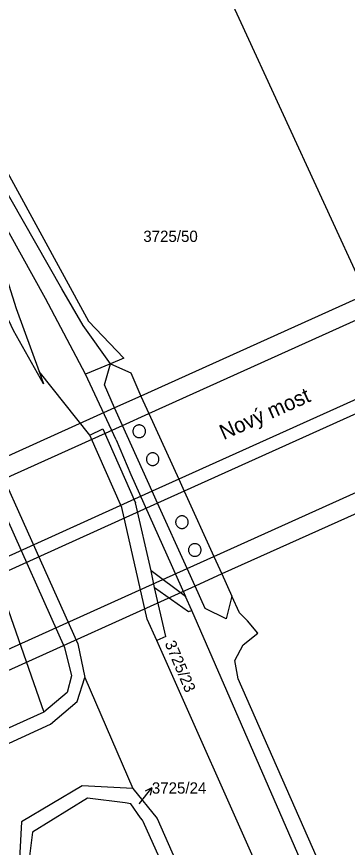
# Model space of a CAD drawing. Extents: x -747779 to -747197, y -965543 to -964919.
# Drawn here: x -747440.7 to -747390.8, y -965475 to -965349.9 of the extents above; entities that cross this region are included whole.
import ezdxf

# ---------------------------------------------------------------- set-up
doc = ezdxf.new("R2010")
doc.units = 0
for name, color, linetype in [('Hranice parcel', 7, 'Continuous'), ('Parcelní čísla', 7, 'Continuous'), ('Pop  PČ popisy', 7, 'Continuous'), ('Vnitřní kresba', 7, 'Continuous')]:
    doc.layers.add(name, color=color, linetype=linetype)

msp = doc.modelspace()

# ---------------------------------------------------------------- linework, layer by layer
at = {"layer": 'Hranice parcel'}
for p, q in [((-747442.75, -965437.1), (-747436.62, -965454.67)), ((-747430.45, -965449.46), (-747423.22, -965466.19))]:
    msp.add_line(p, q, dxfattribs=at)
for points in [[(-747298.39, -965537.69), (-747318.1, -965501.72), (-747320.58, -965502.66), (-747342.67, -965465.16), (-747352.78, -965470.55), (-747357.13, -965461.03), (-747376, -965418.63), (-747377.18, -965415.98), (-747381.59, -965406.09), (-747382.39, -965404.29), (-747386.82, -965394.33), (-747387.63, -965392.51), (-747387.99, -965391.72), (-747426.3, -965308.51), (-747438.98, -965282.25)], [(-747481.32, -965290.75), (-747467.96, -965317.93), (-747448.87, -965361), (-747429.89, -965395.74), (-747424.56, -965401.33), (-747426.57, -965402.17)], [(-747437.34, -965403.35), (-747436.67, -965405.18), (-747441.17, -965397.15), (-747449.31, -965379.9), (-747457.39, -965360.59), (-747463.67, -965351.63), (-747474.03, -965344.07), (-747481.12, -965327.83), (-747494.62, -965293.42)], [(-747580, -965419.59), (-747576.93, -965416.19), (-747570.41, -965408.98), (-747568.93, -965407.34), (-747555.66, -965395.12), (-747533.62, -965375.09), (-747516.44, -965363.14), (-747498.44, -965358.86), (-747484.39, -965361.2), (-747471.99, -965367.52), (-747464.29, -965374.98), (-747459.13, -965383.85), (-747452.93, -965401.54), (-747433.5, -965444.94), (-747432.43, -965449.21), (-747433.12, -965451.71), (-747436.62, -965454.67)], [(-747426.57, -965402.17), (-747430.32, -965403.74), (-747436.36, -965392.33), (-747443.64, -965379.27), (-747445.23, -965379.92)], [(-747445.23, -965379.92), (-747440.81, -965393.86), (-747437.34, -965403.35)], [(-747457, -965384.11), (-747451.17, -965400.56), (-747431.47, -965444.37), (-747430.45, -965449.46)], [(-747425.95, -965408.84), (-747427.45, -965405.35), (-747426.57, -965402.17)], [(-747421.02, -965440.66), (-747424.84, -965423.83), (-747429.68, -965412.94), (-747437.34, -965403.35)], [(-747413.8, -965435.67), (-747414.99, -965433.04), (-747419.46, -965423.17), (-747420.28, -965421.37), (-747424.76, -965411.47), (-747425.95, -965408.84)], [(-747370.93, -965537.69), (-747371.14, -965534.42), (-747371.37, -965533), (-747372.01, -965529.87), (-747376.13, -965520.36), (-747382.27, -965506.43), (-747407.33, -965449.67), (-747407.84, -965446.87), (-747406.56, -965444.53), (-747404.36, -965442.75), (-747405.91, -965440.89), (-747407.09, -965439.7), (-747408.25, -965437.2), (-747409.14, -965440.59), (-747412.27, -965439.07), (-747413.8, -965435.67)], [(-747377.11, -965537.69), (-747403.05, -965481.03), (-747419.59, -965443.86), (-747421.02, -965440.66)], [(-747447.33, -965460.58), (-747441.86, -965459.33), (-747435.59, -965456.49), (-747431.61, -965453.05), (-747430.45, -965449.46)], [(-747436.62, -965454.67), (-747442.27, -965457.24), (-747448.67, -965457.93), (-747450.38, -965456.32)], [(-747423.22, -965466.19), (-747430.85, -965465.78), (-747440, -965471.21), (-747440.51, -965480.52)], [(-747423.22, -965466.19), (-747419.51, -965470.69), (-747413.64, -965484.08), (-747404.72, -965503.92), (-747389.51, -965537.69)], [(-747391.7, -965537.69), (-747398.54, -965522.5), (-747406.47, -965504.9), (-747415.34, -965485.13), (-747421.64, -965471.15), (-747421.73, -965470.95), (-747422.02, -965470.6), (-747423.51, -965468.47), (-747424.37, -965468.36), (-747430.04, -965467.62), (-747438.32, -965472.78), (-747439.08, -965478.79), (-747440.51, -965480.52)]]:
    msp.add_lwpolyline(points, dxfattribs=at)
at = {"layer": 'Pop  PČ popisy'}
for p, q in [((-747422.19, -965468.46), (-747420.34, -965466.09)), ((-747420.34, -965466.09), (-747421.35, -965466.58)), ((-747420.34, -965466.09), (-747420.56, -965467.19)), ((-747422.23, -965468.51), (-747422.19, -965468.46))]:
    msp.add_line(p, q, dxfattribs=at)
at = {"layer": 'Vnitřní kresba'}
for p, q in [((-747433.91, -965390.91), (-747444.82, -965371.76)), ((-747430.68, -965396.39), (-747433.91, -965390.91)), ((-747387.99, -965391.72), (-747421.99, -965407.05)), ((-747420.79, -965409.68), (-747386.82, -965394.33)), ((-747426.57, -965402.17), (-747430.68, -965396.39)), ((-747426.57, -965402.17), (-747423.49, -965403.54)), ((-747425.73, -965413.62), (-747430.32, -965403.74)), ((-747423.49, -965403.54), (-747421.99, -965407.05)), ((-747382.39, -965404.29), (-747416.28, -965419.57)), ((-747381.59, -965406.09), (-747415.46, -965421.36)), ((-747421.99, -965407.05), (-747425.95, -965408.84)), ((-747421.99, -965407.05), (-747420.79, -965409.68)), ((-747425.95, -965408.84), (-747511.58, -965447.46)), ((-747424.76, -965411.47), (-747420.79, -965409.68)), ((-747420.79, -965409.68), (-747416.28, -965419.57)), ((-747510.38, -965450.13), (-747424.76, -965411.47)), ((-747429.68, -965412.94), (-747427.74, -965412)), ((-747427.74, -965412), (-747422.79, -965423.13)), ((-747425.73, -965413.62), (-747423.52, -965418.88)), ((-747410.96, -965431.22), (-747377.18, -965415.98)), ((-747423.52, -965418.88), (-747415.25, -965437.24)), ((-747376, -965418.63), (-747409.76, -965433.85)), ((-747416.28, -965419.57), (-747420.28, -965421.37)), ((-747416.28, -965419.57), (-747415.46, -965421.36)), ((-747420.28, -965421.37), (-747505.95, -965460)), ((-747415.46, -965421.36), (-747419.46, -965423.17)), ((-747415.46, -965421.36), (-747410.96, -965431.22)), ((-747419.46, -965423.17), (-747505.13, -965461.82)), ((-747420.45, -965433.4), (-747422.79, -965423.13)), ((-747414.99, -965433.04), (-747410.96, -965431.22)), ((-747410.96, -965431.22), (-747409.76, -965433.85)), ((-747500.73, -965471.63), (-747414.99, -965433.04)), ((-747419.91, -965435.87), (-747420.45, -965433.4)), ((-747415.25, -965437.24), (-747420.45, -965433.4)), ((-747409.76, -965433.85), (-747413.8, -965435.67)), ((-747409.76, -965433.85), (-747408.25, -965437.2)), ((-747413.8, -965435.67), (-747499.51, -965474.39)), ((-747418.24, -965443.28), (-747419.91, -965435.87)), ((-747419.91, -965435.87), (-747414.81, -965439.52)), ((-747414.31, -965439.35), (-747415.25, -965437.24)), ((-747414.81, -965439.52), (-747414.31, -965439.35)), ((-747373.33, -965533.21), (-747414.31, -965439.35)), ((-747418.24, -965443.28), (-747419.59, -965443.86))]:
    msp.add_line(p, q, dxfattribs=at)
for points in [[(-747422.24, -965411.4), (-747422.33, -965411.4), (-747422.41, -965411.42), (-747422.49, -965411.43), (-747422.57, -965411.46), (-747422.65, -965411.49), (-747422.73, -965411.53), (-747422.8, -965411.58), (-747422.86, -965411.64), (-747422.93, -965411.69), (-747422.98, -965411.76), (-747423.03, -965411.83), (-747423.08, -965411.9), (-747423.11, -965411.98), (-747423.14, -965412.06), (-747423.17, -965412.14), (-747423.18, -965412.22), (-747423.19, -965412.31), (-747423.19, -965412.39), (-747423.18, -965412.48), (-747423.17, -965412.56), (-747423.14, -965412.64), (-747423.11, -965412.72), (-747423.08, -965412.8), (-747423.03, -965412.87), (-747422.98, -965412.94), (-747422.93, -965413.01), (-747422.86, -965413.07), (-747422.8, -965413.12), (-747422.73, -965413.17), (-747422.65, -965413.21), (-747422.57, -965413.24), (-747422.49, -965413.27), (-747422.41, -965413.29), (-747422.33, -965413.3), (-747422.24, -965413.3), (-747422.16, -965413.3), (-747422.07, -965413.29), (-747421.99, -965413.27), (-747421.91, -965413.24), (-747421.83, -965413.21), (-747421.75, -965413.17), (-747421.68, -965413.12), (-747421.61, -965413.07), (-747421.55, -965413.01), (-747421.5, -965412.94), (-747421.45, -965412.87), (-747421.4, -965412.8), (-747421.37, -965412.72), (-747421.34, -965412.64), (-747421.31, -965412.56), (-747421.3, -965412.48), (-747421.29, -965412.39), (-747421.29, -965412.31), (-747421.3, -965412.22), (-747421.31, -965412.14), (-747421.34, -965412.06), (-747421.37, -965411.98), (-747421.4, -965411.9), (-747421.45, -965411.83), (-747421.5, -965411.76), (-747421.55, -965411.69), (-747421.61, -965411.64), (-747421.68, -965411.58), (-747421.75, -965411.53), (-747421.83, -965411.49), (-747421.91, -965411.46), (-747421.99, -965411.43), (-747422.07, -965411.42), (-747422.16, -965411.4)], [(-747420.21, -965415.61), (-747420.3, -965415.61), (-747420.38, -965415.62), (-747420.46, -965415.64), (-747420.54, -965415.67), (-747420.62, -965415.7), (-747420.7, -965415.74), (-747420.77, -965415.79), (-747420.83, -965415.84), (-747420.9, -965415.9), (-747420.95, -965415.97), (-747421, -965416.04), (-747421.05, -965416.11), (-747421.08, -965416.19), (-747421.11, -965416.27), (-747421.14, -965416.35), (-747421.15, -965416.43), (-747421.16, -965416.52), (-747421.16, -965416.6), (-747421.15, -965416.69), (-747421.14, -965416.77), (-747421.11, -965416.85), (-747421.08, -965416.93), (-747421.05, -965417.01), (-747421, -965417.08), (-747420.95, -965417.15), (-747420.9, -965417.22), (-747420.83, -965417.28), (-747420.77, -965417.33), (-747420.7, -965417.38), (-747420.62, -965417.42), (-747420.54, -965417.45), (-747420.46, -965417.48), (-747420.38, -965417.49), (-747420.3, -965417.51), (-747420.21, -965417.51), (-747420.12, -965417.51), (-747420.04, -965417.49), (-747419.96, -965417.48), (-747419.88, -965417.45), (-747419.8, -965417.42), (-747419.72, -965417.38), (-747419.65, -965417.33), (-747419.58, -965417.28), (-747419.52, -965417.22), (-747419.47, -965417.15), (-747419.42, -965417.08), (-747419.37, -965417.01), (-747419.34, -965416.93), (-747419.31, -965416.85), (-747419.28, -965416.77), (-747419.27, -965416.69), (-747419.26, -965416.6), (-747419.26, -965416.52), (-747419.27, -965416.43), (-747419.28, -965416.35), (-747419.31, -965416.27), (-747419.34, -965416.19), (-747419.37, -965416.11), (-747419.42, -965416.04), (-747419.47, -965415.97), (-747419.52, -965415.9), (-747419.58, -965415.84), (-747419.65, -965415.79), (-747419.72, -965415.74), (-747419.8, -965415.7), (-747419.88, -965415.67), (-747419.96, -965415.64), (-747420.04, -965415.62), (-747420.12, -965415.61)], [(-747415.79, -965425.1), (-747415.88, -965425.1), (-747415.96, -965425.11), (-747416.04, -965425.13), (-747416.12, -965425.16), (-747416.2, -965425.19), (-747416.28, -965425.23), (-747416.35, -965425.28), (-747416.42, -965425.33), (-747416.48, -965425.39), (-747416.53, -965425.46), (-747416.58, -965425.53), (-747416.63, -965425.6), (-747416.66, -965425.68), (-747416.69, -965425.76), (-747416.72, -965425.84), (-747416.73, -965425.92), (-747416.74, -965426.01), (-747416.74, -965426.09), (-747416.73, -965426.18), (-747416.72, -965426.26), (-747416.69, -965426.34), (-747416.66, -965426.42), (-747416.63, -965426.5), (-747416.58, -965426.57), (-747416.53, -965426.64), (-747416.48, -965426.71), (-747416.42, -965426.77), (-747416.35, -965426.82), (-747416.28, -965426.87), (-747416.2, -965426.91), (-747416.12, -965426.94), (-747416.04, -965426.97), (-747415.96, -965426.98), (-747415.88, -965427), (-747415.79, -965427), (-747415.7, -965427), (-747415.62, -965426.98), (-747415.54, -965426.97), (-747415.46, -965426.94), (-747415.38, -965426.91), (-747415.3, -965426.87), (-747415.23, -965426.82), (-747415.17, -965426.77), (-747415.1, -965426.71), (-747415.05, -965426.64), (-747415, -965426.57), (-747414.95, -965426.5), (-747414.92, -965426.42), (-747414.89, -965426.34), (-747414.86, -965426.26), (-747414.85, -965426.18), (-747414.84, -965426.09), (-747414.84, -965426.01), (-747414.85, -965425.92), (-747414.86, -965425.84), (-747414.89, -965425.76), (-747414.92, -965425.68), (-747414.95, -965425.6), (-747415, -965425.53), (-747415.05, -965425.46), (-747415.1, -965425.39), (-747415.17, -965425.33), (-747415.23, -965425.28), (-747415.3, -965425.23), (-747415.38, -965425.19), (-747415.46, -965425.16), (-747415.54, -965425.13), (-747415.62, -965425.11), (-747415.7, -965425.1)], [(-747413.85, -965429.29), (-747413.94, -965429.29), (-747414.02, -965429.31), (-747414.1, -965429.32), (-747414.18, -965429.35), (-747414.26, -965429.38), (-747414.34, -965429.42), (-747414.41, -965429.47), (-747414.47, -965429.53), (-747414.54, -965429.58), (-747414.59, -965429.65), (-747414.64, -965429.72), (-747414.69, -965429.79), (-747414.72, -965429.87), (-747414.75, -965429.95), (-747414.78, -965430.03), (-747414.79, -965430.11), (-747414.8, -965430.2), (-747414.8, -965430.28), (-747414.79, -965430.37), (-747414.78, -965430.45), (-747414.75, -965430.53), (-747414.72, -965430.61), (-747414.69, -965430.69), (-747414.64, -965430.76), (-747414.59, -965430.83), (-747414.54, -965430.9), (-747414.47, -965430.96), (-747414.41, -965431.01), (-747414.34, -965431.06), (-747414.26, -965431.1), (-747414.18, -965431.13), (-747414.1, -965431.16), (-747414.02, -965431.18), (-747413.94, -965431.19), (-747413.85, -965431.19), (-747413.77, -965431.19), (-747413.68, -965431.18), (-747413.6, -965431.16), (-747413.52, -965431.13), (-747413.44, -965431.1), (-747413.36, -965431.06), (-747413.29, -965431.01), (-747413.22, -965430.96), (-747413.16, -965430.9), (-747413.11, -965430.83), (-747413.06, -965430.76), (-747413.01, -965430.69), (-747412.98, -965430.61), (-747412.95, -965430.53), (-747412.92, -965430.45), (-747412.91, -965430.37), (-747412.9, -965430.28), (-747412.9, -965430.2), (-747412.91, -965430.11), (-747412.92, -965430.03), (-747412.95, -965429.95), (-747412.98, -965429.87), (-747413.01, -965429.79), (-747413.06, -965429.72), (-747413.11, -965429.65), (-747413.16, -965429.58), (-747413.22, -965429.53), (-747413.29, -965429.47), (-747413.36, -965429.42), (-747413.44, -965429.38), (-747413.52, -965429.35), (-747413.6, -965429.32), (-747413.68, -965429.31), (-747413.77, -965429.29)]]:
    msp.add_lwpolyline(points, close=True, dxfattribs=at)

# ---------------------------------------------------------------- texts
at = {"layer": 'Parcelní čísla'}
for s, p in [('3725/50', (-747421.62, -965383.82)), ('3725/24', (-747420.33, -965466.95))]:
    msp.add_text(s, height=1.7, dxfattribs=at).set_placement(p)
msp.add_text('3725/23', height=1.7, rotation=293, dxfattribs=at).set_placement((-747418.42, -965444.3))
at = {"layer": 'Pop  PČ popisy'}
msp.add_text('Nový most', height=2.3, rotation=24, dxfattribs=at).set_placement((-747409.49, -965413.7))

doc.saveas('drawing.dxf')
